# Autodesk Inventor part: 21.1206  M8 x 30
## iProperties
Created: 2006-02
Part Number: 21.1206  M8 x 30
Material: Steel, Mild
Description: Cylinder Head Cap Screw
Document SubType Name: Modeling
Standard: DIN 7984
Designer: Andy Moles
Standards Organization: DIN
Language: en-US
Size Designation: M8 x 30
Categories: <MemberInstance><Categories><Category DisplayName="Fasteners" InternalName="e4da775c-781d-43d5-af7c-5136215cf5a6" Mnemonic="FSTN"><Category DisplayName="Bolts"
Density: 7.86 g/cm^3
Mass: 16.2139 g
Surface Area: 12.69 cm^2
Volume: 2.06284 cm^3
Author: Andy Moles
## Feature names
1. Body [Revolution]
2. Slot [Extrusion]
3. Fillet1
4. Chamfer1
